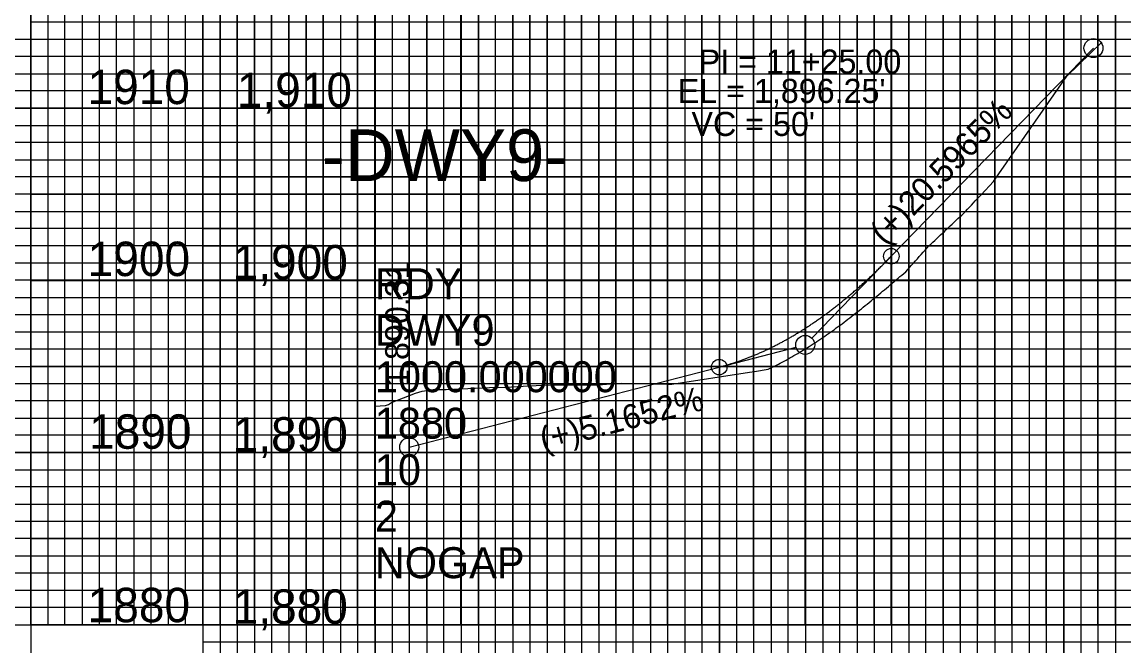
# Model space of a CAD drawing. Extents: x 553912 to 567693, y 512355 to 537539.
# Drawn here: x 566173.9 to 566493.9, y 513958.5 to 514139.7 of the extents above; entities that cross this region are included whole.
import ezdxf

# ---------------------------------------------------------------- set-up
doc = ezdxf.new("R2010")
doc.units = 0
for name, color, linetype in [('Exist Profile Cell', 7, 'Continuous'), ('Exist Vertical Profile Ground Line', 7, 'Continuous'), ('Exist Vertical Profile Horizontal Axis Label Major', 7, 'Continuous'), ('Exist Vertical Profile Vertical Axis Label', 7, 'Continuous'), ('Old_Level_42', 7, 'Continuous'), ('Old_Level_53', 7, 'Continuous'), ('Old_Level_54', 7, 'Continuous'), ('Prop ROW Permanent Easement CELL', 7, 'Continuous'), ('Prop Vertical Profile Curve Label', 7, 'Continuous'), ('Prop Vertical Profile Grade', 7, 'Continuous'), ('Prop Vertical Profile Grade Label', 7, 'Continuous'), ('Prop VPI Label', 7, 'Continuous'), ('Sheet DOT Grid CELL', 7, 'Continuous'), ('Sheet Layout Profile Border Port 1', 7, 'Continuous'), ('Sheet Profile CELL', 7, 'Continuous'), ('Sheet Profile Grid Major CELL', 7, 'Continuous'), ('Sheet Profile Grid Middle CELL', 7, 'Continuous'), ('Sheet Profile Grid Minor CELL', 7, 'Continuous'), ('Sheet Summary Guardrail CELL', 7, 'Continuous')]:
    doc.layers.add(name, color=color, linetype=linetype)

msp = doc.modelspace()

# ---------------------------------------------------------------- linework, layer by layer
at = {"layer": 'Exist Profile Cell'}
for q in [(566276.35, 514214.72), (566487.52, 513964.72), (566276.35, 513964.72)]:
    msp.add_line((566276.35, 513964.72), q, dxfattribs=at)
at = {"layer": 'Exist Vertical Profile Ground Line'}
for points in [[(566437.84, 514075.26), (566438.4, 514075.79), (566438.96, 514076.31), (566439.52, 514076.83), (566440.08, 514077.36), (566440.64, 514077.88), (566441.2, 514078.41), (566441.76, 514078.94), (566442.32, 514079.46), (566442.88, 514079.99), (566443.44, 514080.52), (566444, 514081.05), (566444.56, 514081.57), (566445.12, 514082.1), (566445.69, 514082.62), (566446.25, 514083.15), (566446.81, 514083.68), (566447.37, 514084.2), (566447.93, 514084.74), (566448.49, 514085.35), (566449.05, 514085.96), (566449.61, 514086.56), (566450.17, 514087.17), (566450.73, 514087.77), (566451.29, 514088.38), (566451.85, 514088.98), (566452.41, 514089.58), (566455.98, 514093.39), (566477.3, 514124.02), (566487.51, 514133.9)], [(566276.35, 514028.16), (566279.45, 514028.4), (566280.34, 514028.69), (566281.16, 514029.23), (566288.2, 514031.92), (566290.14, 514032.51), (566293.96, 514033.1), (566294.79, 514033.05), (566297.09, 514033.02), (566309.69, 514033.63), (566314.43, 514033.73), (566321.03, 514034.12), (566327.41, 514034.32), (566341.4, 514034.39), (566344.69, 514034.65), (566348.03, 514034.87), (566361.36, 514034.58), (566362.56, 514034.59), (566385.16, 514038.09), (566386.59, 514038.2), (566390.59, 514038.91), (566392.99, 514040.11), (566393.55, 514040.39), (566394.11, 514040.68), (566394.67, 514040.97), (566395.23, 514041.27), (566395.79, 514041.57), (566396.35, 514041.88), (566396.91, 514042.2), (566397.47, 514042.51), (566398.03, 514042.84), (566399.16, 514043.49), (566399.72, 514043.82), (566400.28, 514044.15), (566400.84, 514044.49), (566401.4, 514044.83), (566401.96, 514045.18), (566402.52, 514045.53), (566403.08, 514045.88), (566403.64, 514046.24), (566404.2, 514046.61), (566404.76, 514046.98), (566405.32, 514047.35), (566405.88, 514047.73), (566406.44, 514048.11), (566407, 514048.49), (566407.56, 514048.88), (566408.13, 514049.27), (566408.69, 514049.67), (566409.25, 514050.06), (566409.81, 514050.47), (566410.37, 514050.87), (566410.93, 514051.28), (566411.49, 514051.7), (566412.05, 514052.11), (566412.61, 514052.54), (566413.17, 514052.96), (566413.73, 514053.39), (566414.29, 514053.82), (566414.85, 514054.26), (566415.41, 514054.7), (566415.97, 514055.14), (566416.53, 514055.58), (566417.09, 514056.03), (566417.66, 514056.47), (566418.22, 514056.92), (566418.78, 514057.37), (566419.34, 514057.83), (566419.9, 514058.29), (566420.46, 514058.74), (566421.02, 514059.2), (566421.58, 514059.66), (566422.14, 514060.13), (566422.7, 514060.59), (566423.26, 514061.06), (566423.82, 514061.53), (566424.38, 514062), (566424.94, 514062.47), (566425.5, 514062.94), (566426.06, 514063.41), (566426.63, 514063.88), (566427.19, 514064.36), (566427.75, 514064.83), (566428.31, 514065.31), (566428.87, 514065.78), (566429.43, 514066.26), (566429.99, 514066.73), (566430.55, 514067.21), (566431.11, 514067.83), (566431.67, 514068.46), (566432.23, 514069.08), (566432.79, 514069.71), (566433.35, 514070.33), (566433.91, 514070.96), (566434.47, 514071.59), (566435.03, 514072.22), (566435.59, 514072.85), (566436.16, 514073.48), (566436.72, 514074.11), (566437.29, 514074.75), (566437.84, 514075.26)]]:
    msp.add_lwpolyline(points, dxfattribs=at)
at = {"layer": 'Old_Level_42'}
for p, q in [((566226.42, 514839.71), (566226.42, 513814.71)), ((566276.42, 514839.71), (566276.42, 513814.71)), ((566326.42, 514839.71), (566326.42, 513814.71)), ((566376.42, 514839.71), (566376.42, 513814.71)), ((566426.42, 514839.71), (566426.42, 513814.71)), ((566476.42, 514839.71), (566476.42, 513814.71)), ((566176.42, 514114.71), (567676.42, 514114.71)), ((566176.42, 514064.71), (567676.42, 514064.71)), ((566176.42, 514014.71), (567676.42, 514014.71)), ((566176.42, 513964.71), (567676.42, 513964.71))]:
    msp.add_line(p, q, dxfattribs=at)
at = {"layer": 'Old_Level_53'}
msp.add_lwpolyline([(567676.42, 514839.71), (566176.42, 514839.71), (566176.42, 513789.71), (567676.42, 513789.71)], close=True, dxfattribs=at)
at = {"layer": 'Old_Level_54'}
for points in [[(566176.42, 514839.71), (566226.42, 514839.71), (566226.42, 513814.71), (566276.42, 513814.71), (566276.42, 514839.71), (566326.42, 514839.71), (566326.42, 513814.71), (566376.42, 513814.71), (566376.42, 514839.71), (566426.42, 514839.71), (566426.42, 513814.71), (566476.42, 513814.71), (566476.42, 514839.71), (566526.42, 514839.71), (566526.42, 513814.71), (566576.42, 513814.71), (566576.42, 514839.71), (566626.42, 514839.71), (566626.42, 513814.71), (566676.42, 513814.71), (566676.42, 514839.71), (566726.42, 514839.71), (566726.42, 513814.71), (566776.42, 513814.71)], [(567676.42, 514064.71), (566176.42, 514064.71), (566176.42, 514114.71), (567676.42, 514114.71)], [(567676.42, 513964.71), (566176.42, 513964.71), (566176.42, 514014.71), (567676.42, 514014.71)]]:
    msp.add_lwpolyline(points, dxfattribs=at)
at = {"layer": 'Prop ROW Permanent Easement CELL'}
for points in [[(566251.42, 513814.71), (566251.42, 514839.71), (566301.42, 514839.71), (566301.42, 513814.71), (566351.42, 513814.71), (566351.42, 514839.71), (566401.42, 514839.71), (566401.42, 513814.71), (566451.42, 513814.71), (566451.42, 514839.71), (566501.42, 514839.71), (566501.42, 513814.71), (566551.42, 513814.71), (566551.42, 514839.71), (566601.42, 514839.71), (566601.42, 513814.71), (566651.42, 513814.71), (566651.42, 514839.71), (566701.42, 514839.71), (566701.42, 513814.71), (566751.42, 513814.71), (566751.42, 514839.71), (566801.42, 514839.71)], [(567676.42, 514139.71), (566176.42, 514139.71), (566176.42, 514089.71), (567676.42, 514089.71)], [(567676.42, 514039.71), (566176.42, 514039.71), (566176.42, 513989.71), (567676.42, 513989.71)]]:
    msp.add_lwpolyline(points, dxfattribs=at)
at = {"layer": 'Prop Vertical Profile Curve Label'}
for centre in [(566426.35, 514071.71), (566376.36, 514039.51)]:
    msp.add_circle(centre, 2.25, dxfattribs=at)
at = {"layer": 'Prop Vertical Profile Grade'}
for p, q in [((566426.35, 514071.71), (566485.04, 514132.16)), ((566286.35, 514016.27), (566376.36, 514039.51))]:
    msp.add_line(p, q, dxfattribs=at)
msp.add_spline([(566376.36, 514039.51), (566377.36, 514039.78), (566378.36, 514040.06), (566379.36, 514040.36), (566380.36, 514040.67), (566381.36, 514041), (566382.36, 514041.34), (566383.36, 514041.7), (566384.36, 514042.07), (566385.36, 514042.46), (566386.35, 514042.87), (566387.35, 514043.29), (566388.35, 514043.72), (566389.35, 514044.17), (566390.35, 514044.64), (566391.35, 514045.12), (566392.35, 514045.62), (566393.35, 514046.13), (566394.35, 514046.66), (566395.35, 514047.2), (566396.35, 514047.76), (566397.35, 514048.34), (566398.35, 514048.93), (566399.35, 514049.53), (566400.35, 514050.15), (566401.35, 514050.79), (566402.35, 514051.44), (566403.35, 514052.11), (566404.35, 514052.79), (566405.35, 514053.49), (566406.35, 514054.2), (566407.35, 514054.93), (566408.35, 514055.68), (566409.35, 514056.44), (566410.35, 514057.21), (566411.35, 514058), (566412.35, 514058.81), (566413.35, 514059.63), (566414.35, 514060.47), (566415.35, 514061.32), (566416.35, 514062.19), (566417.35, 514063.07), (566418.35, 514063.97), (566419.35, 514064.88), (566420.35, 514065.81), (566421.35, 514066.76), (566422.35, 514067.72), (566423.35, 514068.69), (566424.35, 514069.69), (566425.35, 514070.69), (566426.35, 514071.71)], degree=3, dxfattribs=at)
at = {"layer": 'Prop VPI Label'}
for p, q in [((566426.35, 514071.71), (566403.27, 514047.94)), ((566376.36, 514039.51), (566398.69, 514045.28))]:
    msp.add_line(p, q, dxfattribs=at)
for centre in [(566485.04, 514132.16), (566401.35, 514045.97), (566286.35, 514016.27)]:
    msp.add_circle(centre, 2.75, dxfattribs=at)
at = {"layer": 'Sheet DOT Grid CELL'}
for p, q in [((566201.35, 513964.72), (566201.35, 514464.72)), ((566251.35, 513964.72), (566251.35, 514464.72)), ((566301.35, 513964.72), (566301.35, 514464.72)), ((566351.35, 513964.72), (566351.35, 514464.72)), ((566401.35, 513964.72), (566401.35, 514464.72)), ((566451.35, 513964.72), (566451.35, 514464.72)), ((567201.35, 514114.72), (565701.35, 514114.72)), ((567201.35, 514064.72), (565701.35, 514064.72)), ((567201.35, 514014.72), (565701.35, 514014.72))]:
    msp.add_line(p, q, dxfattribs=at)
at = {"layer": 'Sheet Layout Profile Border Port 1'}
msp.add_lwpolyline([(565751.35, 514303.67), (565751.35, 513964.72), (567151.35, 513964.72), (567151.35, 514303.67)], dxfattribs=at)
at = {"layer": 'Sheet Profile CELL'}
msp.add_line((565701.35, 513964.72), (567201.35, 513964.72), dxfattribs=at)
at = {"layer": 'Sheet Profile Grid Major CELL'}
for points in [[(566001.35, 514464.72), (566051.35, 514464.72), (566051.35, 513964.72), (566101.35, 513964.72), (566101.35, 514464.72), (566151.35, 514464.72), (566151.35, 513964.72), (566201.35, 513964.72), (566201.35, 514464.72), (566251.35, 514464.72), (566251.35, 513964.72), (566301.35, 513964.72), (566301.35, 514464.72), (566351.35, 514464.72), (566351.35, 513964.72), (566401.35, 513964.72), (566401.35, 514464.72), (566451.35, 514464.72), (566451.35, 513964.72), (566501.35, 513964.72)], [(567201.35, 514164.72), (565701.35, 514164.72), (565701.35, 514114.72), (567201.35, 514114.72)], [(567201.35, 514064.72), (565701.35, 514064.72), (565701.35, 514064.72), (565701.35, 514014.72), (567201.35, 514014.72)]]:
    msp.add_lwpolyline(points, dxfattribs=at)
at = {"layer": 'Sheet Profile Grid Middle CELL'}
for points in [[(565976.35, 513964.72), (566026.35, 513964.72), (566026.35, 514464.72), (566076.35, 514464.72), (566076.35, 513964.72), (566126.35, 513964.72), (566126.35, 514464.72), (566176.35, 514464.72), (566176.35, 513964.72), (566226.35, 513964.72), (566226.35, 514464.72), (566276.35, 514464.72), (566276.35, 513964.72), (566326.35, 513964.72), (566326.35, 513964.72), (566326.35, 514464.72), (566376.35, 514464.72), (566376.35, 513964.72), (566426.35, 513964.72), (566426.35, 514464.72), (566476.35, 514464.72), (566476.35, 513964.72), (566526.35, 513964.72)], [(567201.35, 514089.72), (565701.35, 514089.72), (565701.35, 514039.72), (567201.35, 514039.72)], [(567201.35, 513989.72), (565701.35, 513989.72)]]:
    msp.add_lwpolyline(points, dxfattribs=at)
at = {"layer": 'Sheet Profile Grid Minor CELL'}
for p, q in [((565751.35, 514134.72), (567151.35, 514134.72)), ((567151.35, 514129.72), (565751.35, 514129.72)), ((565751.35, 514124.72), (567151.35, 514124.72)), ((567151.35, 514119.72), (565751.35, 514119.72)), ((565751.35, 514109.72), (567151.35, 514109.72)), ((567151.35, 514104.72), (565751.35, 514104.72)), ((565751.35, 514099.72), (567151.35, 514099.72)), ((567151.35, 514094.72), (565751.35, 514094.72)), ((565751.35, 514084.72), (567151.35, 514084.72)), ((567151.35, 514079.72), (565751.35, 514079.72)), ((567151.35, 514074.72), (565751.35, 514074.72)), ((567151.35, 514069.72), (565751.35, 514069.72)), ((565751.35, 514059.72), (567151.35, 514059.72)), ((567151.35, 514054.72), (565751.35, 514054.72)), ((565751.35, 514049.72), (567151.35, 514049.72)), ((567151.35, 514044.72), (565751.35, 514044.72)), ((565751.35, 514034.72), (567151.35, 514034.72)), ((567151.35, 514029.72), (565751.35, 514029.72)), ((565751.35, 514024.72), (567151.35, 514024.72)), ((567151.35, 514019.72), (565751.35, 514019.72)), ((565751.35, 514009.72), (567151.35, 514009.72)), ((567151.35, 514004.72), (565751.35, 514004.72)), ((565751.35, 513999.72), (567151.35, 513999.72)), ((567151.35, 513994.72), (565751.35, 513994.72)), ((565751.35, 513984.72), (567151.35, 513984.72)), ((567151.35, 513979.72), (565751.35, 513979.72)), ((565751.35, 513974.72), (567151.35, 513974.72))]:
    msp.add_line(p, q, dxfattribs=at)
for points in [[(566181.35, 514464.72), (566181.35, 513964.72), (566186.35, 513964.72), (566186.35, 514464.72)], [(566191.35, 514464.72), (566191.35, 513964.72), (566196.35, 513964.72), (566196.35, 514464.72)], [(566206.35, 514464.72), (566206.35, 513964.72), (566211.35, 513964.72), (566211.35, 514464.72)], [(566216.35, 514464.72), (566216.35, 513964.72), (566221.35, 513964.72), (566221.35, 514464.72)], [(566231.35, 514464.72), (566231.35, 513964.72), (566236.35, 513964.72), (566236.35, 514464.72)], [(566241.35, 514464.72), (566241.35, 513964.72), (566246.35, 513964.72), (566246.35, 514464.72)], [(566256.35, 514464.72), (566256.35, 513964.72), (566261.35, 513964.72), (566261.35, 514464.72)], [(566266.35, 514464.72), (566266.35, 513964.72), (566271.35, 513964.72), (566271.35, 514464.72)], [(566281.35, 514464.72), (566281.35, 513964.72), (566286.35, 513964.72), (566286.35, 514464.72)], [(566291.35, 514464.72), (566291.35, 513964.72), (566296.35, 513964.72), (566296.35, 514464.72)], [(566306.35, 514464.72), (566306.35, 513964.72), (566311.35, 513964.72), (566311.35, 514464.72)], [(566316.35, 514464.72), (566316.35, 513964.72), (566321.35, 513964.72), (566321.35, 514464.72)], [(566331.35, 514464.72), (566331.35, 513964.72), (566336.35, 513964.72), (566336.35, 514464.72)], [(566341.35, 514464.72), (566341.35, 513964.72), (566346.35, 513964.72), (566346.35, 514464.72)], [(566356.35, 514464.72), (566356.35, 513964.72), (566361.35, 513964.72), (566361.35, 514464.72)], [(566366.35, 514464.72), (566366.35, 513964.72), (566371.35, 513964.72), (566371.35, 514464.72)], [(566381.35, 514464.72), (566381.35, 513964.72), (566386.35, 513964.72), (566386.35, 514464.72)], [(566391.35, 514464.72), (566391.35, 513964.72), (566396.35, 513964.72), (566396.35, 514464.72)], [(566406.35, 514464.72), (566406.35, 513964.72), (566406.35, 513964.72), (566411.35, 513964.72), (566411.35, 514464.72)], [(566416.35, 514464.72), (566416.35, 513964.72), (566421.35, 513964.72), (566421.35, 514464.72)], [(566431.35, 514464.72), (566431.35, 513964.72), (566436.35, 513964.72), (566436.35, 514464.72)], [(566441.35, 514464.72), (566441.35, 513964.72), (566446.35, 513964.72), (566446.35, 514464.72)], [(566456.35, 514464.72), (566456.35, 513964.72), (566461.35, 513964.72), (566461.35, 514464.72)], [(566466.35, 514464.72), (566466.35, 513964.72), (566471.35, 513964.72), (566471.35, 514464.72)], [(566481.35, 514464.72), (566481.35, 513964.72), (566486.35, 513964.72), (566486.35, 514464.72)], [(566491.35, 514464.72), (566491.35, 513964.72), (566496.35, 513964.72)], [(567151.35, 513969.72), (565751.35, 513969.72)]]:
    msp.add_lwpolyline(points, dxfattribs=at)
at = {"layer": 'Sheet Summary Guardrail CELL'}
for points in [[(566231.42, 514839.71), (566236.42, 514839.71), (566241.42, 514839.71), (566246.42, 514839.71), (566256.42, 514839.71), (566223.37, 514839.71), (566228.37, 514839.71), (566186.42, 514839.71), (566191.42, 514839.71), (566196.42, 514839.71), (566206.42, 514839.71), (566211.42, 514839.71), (566216.42, 514839.71), (566221.42, 514839.71), (566231.42, 514839.71), (566231.42, 513814.71)], [(566236.42, 513814.71), (566236.42, 514839.71), (566241.42, 514839.71), (566241.42, 513814.71)], [(566246.42, 513814.71), (566246.42, 514839.71), (566256.42, 514839.71), (566256.42, 513814.71)], [(566261.42, 513814.71), (566261.42, 514839.71), (566266.42, 514839.71), (566266.42, 513814.71)], [(566271.42, 513814.71), (566271.42, 514839.71), (566281.42, 514839.71), (566281.42, 513814.71)], [(566286.42, 513814.71), (566286.42, 514839.71), (566291.42, 514839.71), (566291.42, 513814.71)], [(566296.42, 513814.71), (566296.42, 514839.71), (566306.42, 514839.71), (566306.42, 513814.71)], [(566311.42, 513814.71), (566311.42, 514839.71), (566316.42, 514839.71), (566316.42, 513814.71)], [(566321.42, 513814.71), (566321.42, 514839.71), (566331.42, 514839.71), (566331.42, 513814.71)], [(566336.42, 513814.71), (566336.42, 514839.71), (566341.42, 514839.71), (566341.42, 513814.71)], [(566346.42, 513814.71), (566346.42, 514839.71), (566356.42, 514839.71), (566356.42, 513814.71)], [(566361.42, 513814.71), (566361.42, 514839.71), (566366.42, 514839.71), (566366.42, 513814.71)], [(566371.42, 513814.71), (566371.42, 514839.71), (566381.42, 514839.71), (566381.42, 513814.71)], [(566386.42, 513814.71), (566386.42, 514839.71), (566391.42, 514839.71), (566391.42, 513814.71)], [(566396.42, 513814.71), (566396.42, 514839.71), (566406.42, 514839.71), (566406.42, 513814.71)], [(566411.42, 513814.71), (566411.42, 514839.71), (566416.42, 514839.71), (566416.42, 513814.71)], [(566421.42, 513814.71), (566421.42, 514839.71), (566431.42, 514839.71), (566431.42, 513814.71)], [(566436.42, 513814.71), (566436.42, 514839.71), (566436.42, 514839.71), (566441.42, 514839.71), (566441.42, 513814.71)], [(566446.42, 513814.71), (566446.42, 514839.71), (566456.42, 514839.71), (566456.42, 513814.71)], [(566461.42, 513814.71), (566461.42, 514839.71), (566466.42, 514839.71), (566466.42, 513814.71)], [(566471.42, 513814.71), (566471.42, 514839.71), (566481.42, 514839.71), (566481.42, 513814.71)], [(566486.42, 513814.71), (566486.42, 514839.71), (566491.42, 514839.71), (566491.42, 513814.71)], [(567626.42, 514144.71), (566226.42, 514144.71), (566226.42, 514134.71), (567626.42, 514134.71)], [(567626.42, 514129.71), (566226.42, 514129.71), (566226.42, 514124.71), (567626.42, 514124.71)], [(567626.42, 514119.71), (566226.42, 514119.71), (566226.42, 514109.71), (567626.42, 514109.71)], [(567626.42, 514104.71), (566226.42, 514104.71), (566226.42, 514099.71), (567626.42, 514099.71)], [(567626.42, 514094.71), (566226.42, 514094.71), (566226.42, 514084.71), (567626.42, 514084.71)], [(567626.42, 514079.71), (566226.42, 514079.71), (566226.42, 514074.71), (567626.42, 514074.71)], [(567626.42, 514069.71), (566226.42, 514069.71), (566226.42, 514059.71), (567626.42, 514059.71)], [(567626.42, 514054.71), (566226.42, 514054.71), (566226.42, 514049.71), (567626.42, 514049.71)], [(567626.42, 514044.71), (566226.42, 514044.71), (566226.42, 514034.71), (567626.42, 514034.71)], [(567626.42, 514029.71), (566226.42, 514029.71), (566226.42, 514024.71), (567626.42, 514024.71)], [(567626.42, 514019.71), (566226.42, 514019.71)], [(566226.42, 514009.71), (567626.42, 514009.71)], [(567626.42, 514004.71), (566226.42, 514004.71), (566226.42, 513999.71), (567626.42, 513999.71)], [(567626.42, 513994.71), (566226.42, 513994.71)], [(566226.42, 513984.71), (567626.42, 513984.71)], [(567626.42, 513979.71), (566226.42, 513979.71), (566226.42, 513974.71), (567626.42, 513974.71)], [(567626.42, 513969.71), (566226.42, 513969.71), (566226.42, 513959.71), (567626.42, 513959.71)]]:
    msp.add_lwpolyline(points, dxfattribs=at)

# ---------------------------------------------------------------- texts
at = {"layer": 'Exist Profile Cell'}
for s, p in [('RDY', (566276.35, 514059.22)), ('DWY9', (566276.35, 514045.72)), ('1000.000000', (566276.35, 514032.22)), ('1880', (566276.35, 514018.72)), ('10', (566276.35, 514005.22)), ('2', (566276.35, 513991.72)), ('NOGAP', (566276.35, 513978.22))]:
    msp.add_text(s, height=9, dxfattribs=at).set_placement(p)
at = {"layer": 'Exist Vertical Profile Horizontal Axis Label Major'}
for s, height, p in [('1910', 10, (566192.9, 514115.88)), ('-DWY9-', 15, (566260.96, 514093.54)), ('1900', 10, (566192.94, 514065.95)), ('1890', 10, (566193.36, 514015.8)), ('1880', 10, (566192.94, 513965.43))]:
    msp.add_text(s, height=height, dxfattribs=at).set_placement(p)
at = {"layer": 'Exist Vertical Profile Vertical Axis Label'}
for s, p in [('1,910', (566236.25, 514114.97)), ('1,900', (566235.05, 514064.97)), ('1,890', (566235.05, 514014.97)), ('1,880', (566235.05, 513964.97))]:
    msp.add_text(s, height=10, dxfattribs=at).set_placement(p)
at = {"layer": 'Prop Vertical Profile Curve Label'}
msp.add_text("VC = 50'", height=7, dxfattribs=at).set_placement((566368.31, 514106.63))
at = {"layer": 'Prop Vertical Profile Grade Label'}
for s, rotation, p in [('(+)20.5965%', 45.8419, (566424.51, 514074.69)), ('(+)5.1652%', 14.4808, (566325.29, 514015.01))]:
    msp.add_text(s, height=7, rotation=rotation, dxfattribs=at).set_placement(p)
at = {"layer": 'Prop VPI Label'}
for s, p in [('PI = 11+25.00', (566370.42, 514124.74)), ("EL = 1,896.25'", (566364.34, 514116.22))]:
    msp.add_text(s, height=7, dxfattribs=at).set_placement(p)
msp.add_text('1,890.31', height=7, rotation=90, dxfattribs=at).set_placement((566286.35, 514033.77))

doc.saveas('drawing.dxf')
